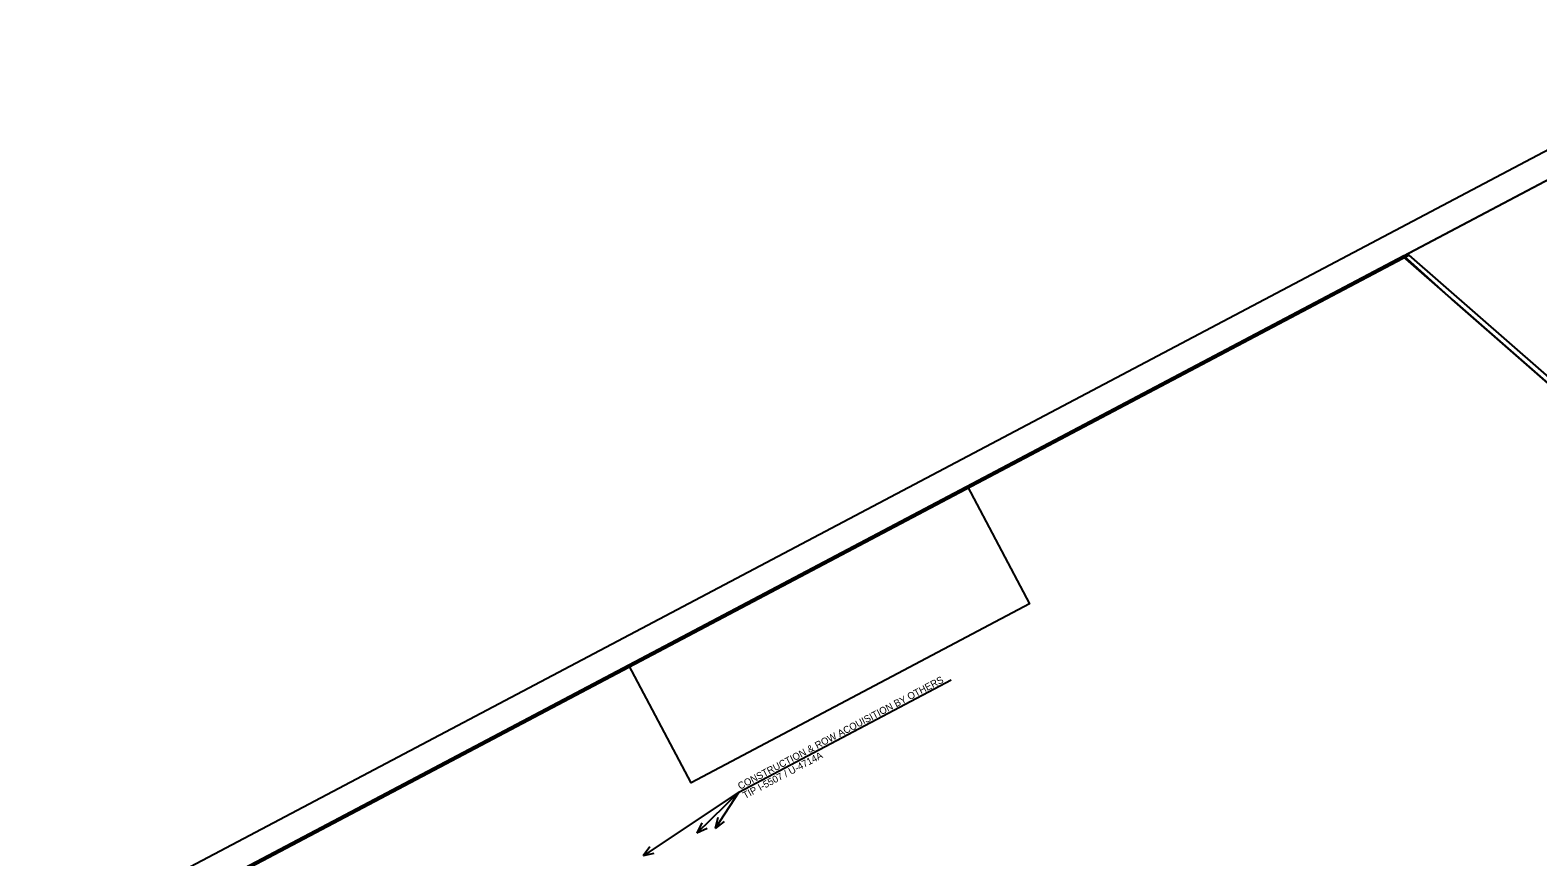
# Model space of a CAD drawing. Extents: x 1487051 to 1489241, y 497582 to 499399.
# Drawn here: x 1487051 to 1488337, y 498631 to 499336 of the extents above; entities that cross this region are included whole.
import ezdxf

# ---------------------------------------------------------------- set-up
doc = ezdxf.new("R2010")
doc.units = 0
for name, color, linetype in [('Exist DTM Regular Point CELL', 7, 'Continuous'), ('Exist DTM Regular Point Cogo Elevation', 7, 'Continuous'), ('Exist Other Culture Sign Post Cogo Comment', 7, 'Continuous'), ('Exist Roads EOP Cogo Point CELL', 7, 'Continuous'), ('Exist Structure Minor Pipes RCP 15 Inch Cogo Comment', 7, 'Continuous'), ('Exist Vegetation Woods Line Cogo Comment', 7, 'Continuous')]:
    doc.layers.add(name, color=color, linetype=linetype)

msp = doc.modelspace()

# ---------------------------------------------------------------- linework, layer by layer
at = {"layer": 'Exist DTM Regular Point CELL'}
for p, q in [((1487655.6, 498686.3), (1487836.8, 498782)), ((1487655.6, 498686.3), (1487573.9, 498631.8)), ((1487655.6, 498686.3), (1487619.9, 498651.3)), ((1487655.6, 498686.3), (1487635.5, 498655.3)), ((1487624, 498659.9), (1487619.9, 498651.3)), ((1487628.6, 498655.2), (1487619.9, 498651.3)), ((1487637.7, 498664.7), (1487635.5, 498655.3)), ((1487643.2, 498661.1), (1487635.5, 498655.3)), ((1487579.6, 498639.5), (1487573.9, 498631.8)), ((1487583.2, 498634), (1487573.9, 498631.8))]:
    msp.add_line(p, q, dxfattribs=at)
at = {"layer": 'Exist DTM Regular Point Cogo Elevation'}
for points in [[(1487208.7, 498608.1), (1488222.1, 499143.2), (1488965.4, 498493.7), (1489025.4, 498380), (1487698.9, 497679.6)], [(1487208.7, 498608.1), (1488222.1, 499143.2), (1488965.4, 498493.7), (1489025.4, 498380), (1487698.9, 497679.6)], [(1487214, 498609.2), (1488227.4, 499144.3), (1488970.7, 498494.8), (1489030.7, 498381.1), (1487704.3, 497680.7)]]:
    msp.add_lwpolyline(points, close=True, dxfattribs=at)
at = {"layer": 'Exist Other Culture Sign Post Cogo Comment'}
msp.add_lwpolyline([(1488264.2, 499106.4), (1488223.1, 499143.8), (1487208.6, 498608.1), (1487698.9, 497679.6), (1489025.4, 498380), (1488872, 498670.6), (1488744.3, 498686.9)], close=True, dxfattribs=at)
at = {"layer": 'Exist Roads EOP Cogo Point CELL'}
msp.add_lwpolyline([(1487562.2, 497582), (1489050.9, 498368), (1488539.7, 499336.3), (1487050.9, 498550.3)], close=True, dxfattribs=at)
at = {"layer": 'Exist Structure Minor Pipes RCP 15 Inch Cogo Comment'}
for points in [[(1488535.1, 499308.5), (1487208.7, 498608.1), (1487698.9, 497679.6), (1489025.4, 498380)], [(1487698.9, 497679.6), (1487208.7, 498608.1), (1488358.2, 499215.1), (1488375.7, 499181.9), (1488552.6, 499275.3), (1489025.4, 498380)], [(1487561.9, 498794.6), (1487850.8, 498947.1), (1487903.8, 498846.8), (1487614.9, 498694.3)]]:
    msp.add_lwpolyline(points, close=True, dxfattribs=at)
at = {"layer": 'Exist Vegetation Woods Line Cogo Comment'}
msp.add_line((1488264.2, 499106.4), (1488744.3, 498686.9), dxfattribs=at)

# ---------------------------------------------------------------- texts
at = {"layer": 'Exist DTM Regular Point CELL'}
for s, p in [('CONSTRUCTION & ROW ACQUISITION BY OTHERS', (1487656.7, 498688.2)), ('TIP I-5507 / U-4714A', (1487660.9, 498680.3))]:
    msp.add_text(s, height=6, rotation=27.8351, dxfattribs=at).set_placement(p)

doc.saveas('drawing.dxf')
